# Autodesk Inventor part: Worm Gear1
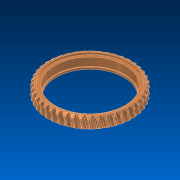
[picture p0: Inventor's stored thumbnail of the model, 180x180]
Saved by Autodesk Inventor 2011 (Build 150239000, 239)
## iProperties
Created: 2011-05
Part Number: Worm Gear1
Material: Steel, Mild
Document SubType Name: Modeling
Designer: 904Chiaki
Categories: <?xml version="1.0" encoding="UTF-16"?> <MemberInstance><Categories><FamilyTemplate><FamilyTemplateParameter ValueType="xs:double" Id="1" ObjectReferenceKey="da
Density: 7.86 g/cm^3
Mass: 36271.6 g
Surface Area: 4778.59 cm^2
Volume: 4614.7 cm^3
CustomPartVersion: 1
Author: 904Chiaki
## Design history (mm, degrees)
mirror "Mirror1"
body "Solid1"
  node "Keyway2"
sketch "Sketch16"
  geometry: C1 r 170 at (0, 0) reference; C2 r 190 at (0, 0)
  constraints: 1 centre point, 1 coincident
  dimensions: "d129" = 380 diameter of C2
extrude "Extrusion7" cut sketch "Sketch16" distance "d130" = 10; taper "d131" = 0 deg
sketch "Sketch17"
  geometry: C1 r 170 at (0, 0) reference; C2 r 190 at (0, 0) reference; C3 r 175 at (0, 0)
  constraints: 1 centre point, 1 coincident
  dimensions: "d132" = 350 diameter of C3
extrude "Extrusion8" cut sketch "Sketch17" distance "d133" = 40; taper "d134" = 0 deg
sketch "Sketch13"
  geometry: C1 r 40 at (0, 0) reference; C2 r 70 at (0, 0) reference
extrude "Extrusion5" join sketch "Sketch13" distance "d118" = 24; taper "d119" = 0 deg
chamfer "Chamfer2" distance "d120" = 2; stored, may be unused: second distance "d121" = 2, angle "d122" = 45 deg
fillet "Fillet4" dims "d123" = 8
workaxis "Work Axis2"
workaxis "Work Axis3"
workplane "Work Plane17"
feature "Hub Keyway"
workaxis "Work Axis4"
workplane "Work Plane18"
sketch "Sketch15"
  geometry: C1 r 170 at (0, 0) reference; C2 r 170 at (0, 0)
  constraints: 1 centre point, 1 coincident
  dimensions: "d126" = 340 diameter of C2
extrude "Extrusion6" cut sketch "Sketch15" stored distance "d127" = 10; taper "d128" = 0 deg
sketch "Sketch10"
  geometry: C1 r 70 at (0, 0) reference; C2 r 40 at (0, 0)
  constraints: 1 centre point, 1 coincident
  dimensions: "d99" = 80 diameter of C2
extrude "Extrusion2" cut sketch "Sketch10" stored distance "d100" = 21; taper "d101" = 0 deg
sketch "Sketch11" dims "d102" = 232
  geometry: C1 r 70 at (0, 0) reference; C2 r 162 at (0, 0) reference; C3 r 22.5 at (116, 0); C4 r 22.5 at (58, 100.459); C5 r 22.5 at (-58, 100.459); C6 r 22.5 at (-116, 0); C7 r 22.5 at (-58, -100.459); C8 r 22.5 at (58, -100.459); 1 further point
  constraints: 6 centre point, 1 coincident, 1 horizontal alignment, 15 other
  dimensions: "d103" = 45 diameter of C3; "d106" = 360 deg dimension on C1.centre C3.centre (derived)
extrude "Extrusion3" cut sketch "Sketch11" stored distance "d108" = 21; taper "d109" = 0 deg
fillet "Fillet3" dims "d115" = 1
sketch "Sketch12"
  geometry: C1 r 40 at (0, 0) reference; C2 r 70 at (0, 0) reference
extrude "Extrusion4" join sketch "Sketch12" distance "d116" = 24; taper "d117" = 0 deg
sketch "Sketch9"
  geometry: C1 r 162 at (0, 0); C2 r 70 at (0, 0); A1 r 199.127 centre (0, 0) between (-37.298, -195.603) and (-19.321, -198.187) reference
  constraints: 2 centre point, 2 coincident
  dimensions: "d94" = 324 diameter of C1; "d95" = 140 diameter of C2
extrude "Extrusion1" cut sketch "Sketch9" distance "d96" = 21; taper "d97" = 0 deg
workplane "Work Plane16"
sketch "Base Body Sketch"
  geometry: L1 (0, -49)-(0, 49) reference; L2 (0, 30)-(199.127, 30); L3 (199.127, 30)-(211.5, 20.572); L4 (-54, 0)-(324, 0) reference; L5 (211.5, 20.572)-(211.5, -20.572); L6 (0, -30)-(199.127, -30); L7 (0, 30)-(0, -30); L8 (199.127, -30)-(211.5, -20.572); C1 r 31.5 at (238.5, 0)
  constraints: 14 end point, 3 symmetric about line, 2 perpendicular, 2 point on line, 1 centre point, 1 collinear
  dimensions: "d50" = 37.3052 deg angle of L3 L2 (= da_fi); "d87" = 423 diameter of L5 L1 (= da_dae); "d89" = 63 diameter of C1 (= 2 x da_aw - da_da); "d92" = 60 distance of L2.start L6.start (= da_b); "d93" = 238.5 distance from line of C1.centre L7 (= da_aw)
revolve "Base Body2" sketch "Base Body Sketch" stored, may be unused: angle "d90" = 90 deg
workplane "Work Plane13"
sketch "Sketch8"
  geometry: C1 r 199.127 at (0, 0) reference; C2 r 198 at (0, 0)
  constraints: 1 centre point, 1 coincident
  dimensions: "d77" = 396 diameter of C2 (= da_dw)
feature "Pitch Diameter" dims "d78" = 60 (= da_b), "d79" = 0
body "Srf1"
workplane "Work Plane14"
workplane "Work Plane15"
revolve "Base Body" stored, may be unused: angle "d35" = 90 deg
node "Tooth Plane"
sketch "Tooth Sketch"
  geometry: L1 (10, 17.378)-(10, -17.378) reference; L2 (-238.76, 0)-(-166.94, 0) reference; L3 (-228.5, 12.413)-(-228.5, -12.413); L4 (-228.5, -12.413)-(-198.8, -12.413); L5 (-198.8, -12.413)-(-177.2, -4.551); L6 (-177.2, -4.551)-(-177.2, 0); L7 (-177.2, 4.551)-(-198.8, 12.413); L8 (-198.8, 12.413)-(-228.5, 12.413); L9 (-177.2, 4.551)-(-177.2, 0); L10 (-188, 0)-(-188, -8.482)
  constraints: 16 end point, 4 perpendicular, 3 equal length, 2 point on line, 1 midpoint, 1 parallel, 1 vertical
  dimensions: "d38" = 238.5 distance between parallel lines of L1 L3 (= da_aw); "d39" = 20 deg angle of L7 L8 (= da_alfat); "d40" = 29.7 distance of L7.end L3.start (= 0.5 x da_df1); "d41" = 40.5 distance between parallel lines of L3 L10 (= 0.5 x da_d1); "d42" = 8.4823 distance of L10.start L10.end (= 0.3 x da_px)
revolve "Tooth" stored, may be unused: angle "d43" = 90 deg
pattern_circular "Tooth Pattern" dims angle "d46" = 360 deg
other parameters: "da_aw" = 238.5 [user parameter; used in 5 equation terms], "da_fi" = 37.3052 deg [user parameter; used in 1 equation term], "da_b" = 60 [user parameter; used in 2 equation terms], "da_df" = 374.4 [user parameter], "da_da" = 414 [user parameter; used in 1 equation term], "da_beta" = 2.18669 [user parameter; used in 1 equation term], "da_alfat" = 20 deg [user parameter; used in 1 equation term], "da_df1" = 59.4 [user parameter; used in 1 equation term], "da_da1" = 99 [user parameter], "da_d1" = 81 [user parameter; used in 1 equation term], "da_px" = 162 deg [user parameter; used in 1 equation term], "d37" = -2.18669 (computed from da_rightdir, da_beta), "d68" = 238.5 (= da_aw), "d69" = 0, "d73" = 0, "d75" = 0.714 (computed from da_z), "da_dw" = 396 [user parameter; used in 1 equation term], "da_rightdir" = 0 [user parameter; used in 1 equation term], "d80" = 0, "d81" = 0, "d82" = 0, "d83" = 0.714 (computed from da_z), "d84" = 0, "d85" = 180 deg, "d86" = 238.5 (= da_aw), "da_dae" = 423 [user parameter; used in 1 equation term], "d124" = 90 deg
